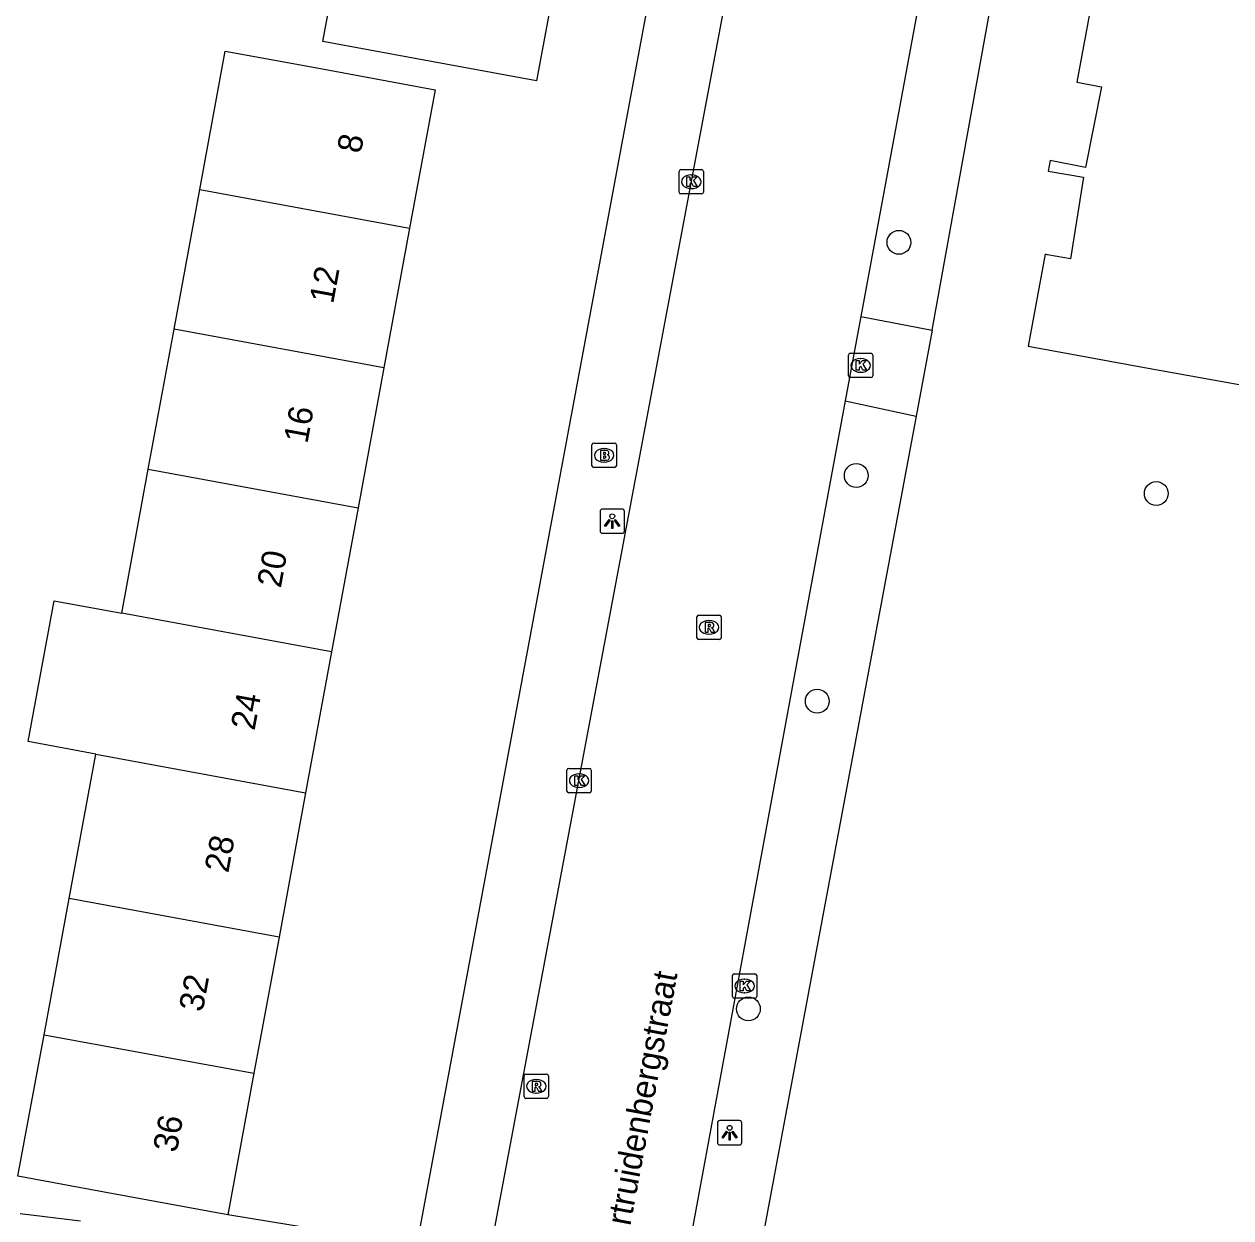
# Model space of a CAD drawing. Extents: x 158087 to 159494, y 382905 to 383981.
# Drawn here: x 158547.97 to 158597.49, y 383276.3 to 383325.28 of the extents above; entities that cross this region are included whole.
import ezdxf

# ---------------------------------------------------------------- set-up
doc = ezdxf.new("R2010")
doc.units = 0
for name, color, linetype in [('IMGEO_Boom', 7, 'Continuous'), ('IMGEO_Brandkraan', 7, 'Continuous'), ('IMGEO_Kolk', 7, 'Continuous'), ('IMGEO_Lichtpunt', 7, 'Continuous'), ('IMGEO_Openbare_ruimte_label', 7, 'Continuous'), ('IMGEO_Pand', 7, 'Continuous'), ('IMGEO_Pand_nummerreeks', 7, 'Continuous'), ('IMGEO_Rijbaan_lokaal_open', 7, 'Continuous'), ('IMGEO_Rioolput', 7, 'Continuous'), ('IMGEO_Voetpad_open', 7, 'Continuous')]:
    doc.layers.add(name, color=color, linetype=linetype)

msp = doc.modelspace()

# ---------------------------------------------------------------- linework, layer by layer
at = {"layer": 'IMGEO_Boom'}
for centre in [(158583.874, 383316.324), (158582.123, 383306.758), (158594.435, 383306.017), (158580.522, 383297.499), (158577.694, 383284.871)]:
    msp.add_circle(centre, 0.489, dxfattribs=at)
at = {"layer": 'IMGEO_Brandkraan'}
for p, q in [((158571.276, 383307.16), (158571.276, 383308.012)), ((158571.351, 383308.086), (158572.203, 383308.086)), ((158572.277, 383308.012), (158572.277, 383307.16)), ((158571.764, 383307.866), (158571.789, 383307.866)), ((158572.203, 383307.086), (158571.351, 383307.086)), ((158571.787, 383307.306), (158571.762, 383307.306))]:
    msp.add_line(p, q, dxfattribs=at)
for points in [[(158571.276, 383307.16), (158571.276, 383308.012)], [(158571.351, 383308.086), (158572.203, 383308.086)], [(158572.277, 383308.012), (158572.277, 383307.16)], [(158571.624, 383307.786), (158571.624, 383307.386), (158571.837, 383307.386)], [(158571.855, 383307.786), (158571.624, 383307.786)], [(158571.803, 383307.705), (158571.749, 383307.705), (158571.749, 383307.629)], [(158571.749, 383307.629), (158571.802, 383307.629)], [(158571.811, 383307.553), (158571.749, 383307.553), (158571.749, 383307.472)], [(158572.203, 383307.086), (158571.351, 383307.086)], [(158571.749, 383307.472), (158571.811, 383307.472)]]:
    msp.add_lwpolyline(points, dxfattribs=at)
for centre, radius, start, end in [((158571.353, 383308.01), 0.0765, 91.552, 178.448), ((158571.353, 383308.01), 0.0765, 91.552, 178.448), ((158572.201, 383308.01), 0.0765, 1.552, 88.448), ((158572.201, 383308.01), 0.0765, 1.552, 88.448), ((158571.804, 383307.667), 0.0379, 267.8285, 90.9355), ((158571.812, 383307.512), 0.0404, 269.8759, 90.5077), ((158571.859, 383307.641), 0.145, 59.4692, 91.5367), ((158571.884, 383307.688), 0.0922, 285.5137, 58.1501), ((158571.889, 383307.496), 0.105, 301.3115, 78.989), ((158571.353, 383307.162), 0.0765, 181.552, 268.448), ((158571.353, 383307.162), 0.0765, 181.552, 268.448), ((158571.843, 383307.637), 0.251, 268.6676, 293.5347), ((158572.201, 383307.162), 0.0765, 271.552, 358.448), ((158572.201, 383307.162), 0.0765, 271.552, 358.448)]:
    msp.add_arc(centre, radius, start, end, dxfattribs=at)
for centre, major_axis, ratio, start_param, end_param in [((158571.763, 383307.586), (-0.387, 0.002), 0.722429, 4.712389, 7.853982), ((158571.788, 383307.586), (-0.39, 0.002), 0.717154, 1.570796, 4.712389)]:
    msp.add_ellipse(centre, major_axis=major_axis, ratio=ratio, start_param=start_param, end_param=end_param, dxfattribs=at)
at = {"layer": 'IMGEO_Kolk'}
for p, q in [((158574.851, 383318.384), (158574.851, 383319.236)), ((158574.926, 383319.31), (158575.778, 383319.31)), ((158575.339, 383319.09), (158575.364, 383319.09)), ((158575.852, 383319.236), (158575.852, 383318.384)), ((158575.362, 383318.53), (158575.337, 383318.53)), ((158575.778, 383318.31), (158574.926, 383318.31)), ((158581.8, 383310.847), (158581.8, 383311.699)), ((158581.875, 383311.773), (158582.727, 383311.773)), ((158582.288, 383311.553), (158582.313, 383311.553)), ((158582.801, 383311.699), (158582.801, 383310.847)), ((158582.311, 383310.993), (158582.286, 383310.993)), ((158582.727, 383310.773), (158581.875, 383310.773)), ((158570.248, 383293.813), (158570.248, 383294.665)), ((158570.323, 383294.739), (158571.175, 383294.739)), ((158571.249, 383294.665), (158571.249, 383293.813)), ((158570.736, 383294.519), (158570.761, 383294.519)), ((158571.175, 383293.739), (158570.323, 383293.739)), ((158570.759, 383293.959), (158570.734, 383293.959)), ((158577.039, 383285.386), (158577.039, 383286.238)), ((158577.114, 383286.312), (158577.966, 383286.312)), ((158578.04, 383286.238), (158578.04, 383285.386)), ((158577.527, 383286.092), (158577.552, 383286.092)), ((158577.966, 383285.312), (158577.114, 383285.312)), ((158577.55, 383285.532), (158577.525, 383285.532))]:
    msp.add_line(p, q, dxfattribs=at)
for points in [[(158574.851, 383318.384), (158574.851, 383319.236)], [(158574.926, 383319.31), (158575.778, 383319.31)], [(158575.172, 383319.01), (158575.295, 383319.01), (158575.295, 383318.859), (158575.425, 383319.01), (158575.589, 383319.01), (158575.443, 383318.859), (158575.596, 383318.61), (158575.444, 383318.61), (158575.359, 383318.774), (158575.295, 383318.707), (158575.295, 383318.61), (158575.172, 383318.61), (158575.172, 383319.01)], [(158575.852, 383319.236), (158575.852, 383318.384)], [(158575.778, 383318.31), (158574.926, 383318.31)], [(158581.8, 383310.847), (158581.8, 383311.699)], [(158581.875, 383311.773), (158582.727, 383311.773)], [(158582.121, 383311.473), (158582.244, 383311.473), (158582.244, 383311.322), (158582.374, 383311.473), (158582.538, 383311.473), (158582.392, 383311.322), (158582.545, 383311.073), (158582.393, 383311.073), (158582.308, 383311.237), (158582.244, 383311.17), (158582.244, 383311.073), (158582.121, 383311.073), (158582.121, 383311.473)], [(158582.801, 383311.699), (158582.801, 383310.847)], [(158582.727, 383310.773), (158581.875, 383310.773)], [(158570.248, 383293.813), (158570.248, 383294.665)], [(158570.323, 383294.739), (158571.175, 383294.739)], [(158571.249, 383294.665), (158571.249, 383293.813)], [(158570.569, 383294.439), (158570.692, 383294.439), (158570.692, 383294.288), (158570.822, 383294.439), (158570.986, 383294.439), (158570.84, 383294.288), (158570.993, 383294.039), (158570.841, 383294.039), (158570.756, 383294.203), (158570.692, 383294.136), (158570.692, 383294.039), (158570.569, 383294.039), (158570.569, 383294.439)], [(158571.175, 383293.739), (158570.323, 383293.739)], [(158577.039, 383285.386), (158577.039, 383286.238)], [(158577.114, 383286.312), (158577.966, 383286.312)], [(158578.04, 383286.238), (158578.04, 383285.386)], [(158577.36, 383286.012), (158577.483, 383286.012), (158577.483, 383285.861), (158577.613, 383286.012), (158577.777, 383286.012), (158577.631, 383285.861), (158577.784, 383285.612), (158577.632, 383285.612), (158577.547, 383285.776), (158577.483, 383285.709), (158577.483, 383285.612), (158577.36, 383285.612), (158577.36, 383286.012)], [(158577.966, 383285.312), (158577.114, 383285.312)]]:
    msp.add_lwpolyline(points, dxfattribs=at)
for centre, start, end in [((158574.928, 383319.234), 91.552, 178.448), ((158574.928, 383319.234), 91.552, 178.448), ((158575.776, 383319.234), 1.552, 88.448), ((158575.776, 383319.234), 1.552, 88.448), ((158574.928, 383318.386), 181.552, 268.448), ((158574.928, 383318.386), 181.552, 268.448), ((158575.776, 383318.386), 271.552, 358.448), ((158575.776, 383318.386), 271.552, 358.448), ((158581.877, 383311.697), 91.552, 178.448), ((158581.877, 383311.697), 91.552, 178.448), ((158582.725, 383311.697), 1.552, 88.448), ((158582.725, 383311.697), 1.552, 88.448), ((158581.877, 383310.849), 181.552, 268.448), ((158581.877, 383310.849), 181.552, 268.448), ((158582.725, 383310.849), 271.552, 358.448), ((158582.725, 383310.849), 271.552, 358.448), ((158570.325, 383294.663), 91.552, 178.448), ((158570.325, 383294.663), 91.552, 178.448), ((158571.173, 383294.663), 1.552, 88.448), ((158571.173, 383294.663), 1.552, 88.448), ((158570.325, 383293.815), 181.552, 268.448), ((158570.325, 383293.815), 181.552, 268.448), ((158571.173, 383293.815), 271.552, 358.448), ((158571.173, 383293.815), 271.552, 358.448), ((158577.116, 383286.236), 91.552, 178.448), ((158577.116, 383286.236), 91.552, 178.448), ((158577.964, 383286.236), 1.552, 88.448), ((158577.964, 383286.236), 1.552, 88.448), ((158577.116, 383285.388), 181.552, 268.448), ((158577.116, 383285.388), 181.552, 268.448), ((158577.964, 383285.388), 271.552, 358.448), ((158577.964, 383285.388), 271.552, 358.448)]:
    msp.add_arc(centre, 0.0765, start, end, dxfattribs=at)
for centre, major_axis, ratio, start_param, end_param in [((158575.338, 383318.81), (-0.387, 0.002), 0.722429, 4.712389, 7.853982), ((158575.363, 383318.81), (-0.39, 0.002), 0.717154, 1.570796, 4.712389), ((158582.287, 383311.273), (-0.387, 0.002), 0.722429, 4.712389, 7.853982), ((158582.312, 383311.273), (-0.39, 0.002), 0.717154, 1.570796, 4.712389), ((158570.735, 383294.239), (-0.387, 0.002), 0.722429, 4.712389, 7.853982), ((158570.76, 383294.239), (-0.39, 0.002), 0.717154, 1.570796, 4.712389), ((158577.526, 383285.812), (-0.387, 0.002), 0.722429, 4.712389, 7.853982), ((158577.551, 383285.812), (-0.39, 0.002), 0.717154, 1.570796, 4.712389)]:
    msp.add_ellipse(centre, major_axis=major_axis, ratio=ratio, start_param=start_param, end_param=end_param, dxfattribs=at)
at = {"layer": 'IMGEO_Lichtpunt'}
for p, q in [((158571.61, 383305.287), (158571.61, 383304.48)), ((158571.61, 383305.287), (158571.61, 383304.48)), ((158572.512, 383305.382), (158571.704, 383305.382)), ((158572.512, 383305.382), (158571.704, 383305.382)), ((158572.606, 383304.48), (158572.606, 383305.287)), ((158572.606, 383304.48), (158572.606, 383305.287)), ((158571.704, 383304.386), (158572.512, 383304.386)), ((158571.704, 383304.386), (158572.512, 383304.386)), ((158577.329, 383280.291), (158576.521, 383280.291)), ((158577.329, 383280.291), (158576.521, 383280.291)), ((158576.427, 383280.196), (158576.427, 383279.389)), ((158576.427, 383280.196), (158576.427, 383279.389)), ((158577.423, 383279.389), (158577.423, 383280.196)), ((158577.423, 383279.389), (158577.423, 383280.196)), ((158576.521, 383279.295), (158577.329, 383279.295)), ((158576.521, 383279.295), (158577.329, 383279.295))]:
    msp.add_line(p, q, dxfattribs=at)
for points in [[(158571.984, 383304.951), (158572.023, 383304.923), (158571.835, 383304.661), (158571.797, 383304.688), (158571.984, 383304.951)], [(158572.086, 383304.903), (158572.133, 383304.903), (158572.133, 383304.581), (158572.086, 383304.581), (158572.086, 383304.903)], [(158572.196, 383304.923), (158572.234, 383304.95), (158572.421, 383304.688), (158572.382, 383304.66), (158572.196, 383304.923)], [(158576.801, 383279.86), (158576.84, 383279.832), (158576.652, 383279.57), (158576.614, 383279.597), (158576.801, 383279.86)], [(158576.903, 383279.812), (158576.95, 383279.812), (158576.95, 383279.49), (158576.903, 383279.49), (158576.903, 383279.812)], [(158577.013, 383279.832), (158577.051, 383279.859), (158577.238, 383279.597), (158577.199, 383279.569), (158577.013, 383279.832)]]:
    msp.add_lwpolyline(points, dxfattribs=at)
for centre in [(158572.109, 383305.085), (158576.926, 383279.994)]:
    msp.add_circle(centre, 0.0994, dxfattribs=at)
for centre, start, end in [((158571.704, 383305.287), 90, 180), ((158571.704, 383305.287), 90, 180), ((158572.512, 383305.287), 0, 90), ((158572.512, 383305.287), 0, 90), ((158571.704, 383304.48), 180, 270), ((158571.704, 383304.48), 180, 270), ((158572.512, 383304.48), 270, 0), ((158572.512, 383304.48), 270, 360), ((158576.521, 383280.196), 90, 180), ((158576.521, 383280.196), 90, 180), ((158577.329, 383280.196), 0, 90), ((158577.329, 383280.196), 0, 90), ((158576.521, 383279.389), 180, 270), ((158576.521, 383279.389), 180, 270), ((158577.329, 383279.389), 270, 0), ((158577.329, 383279.389), 270, 360)]:
    msp.add_arc(centre, 0.0946, start, end, dxfattribs=at)
at = {"layer": 'IMGEO_Pand'}
for points in [[(158599.482, 383347.068), (158596.791, 383347.973), (158596.125, 383343.926), (158595.09, 383344.142), (158593.778, 383337.052), (158594.823, 383336.845), (158594.137, 383333.568), (158592.674, 383333.836), (158592.591, 383333.398), (158594.085, 383333.132), (158593.521, 383329.798), (158592.481, 383329.996), (158591.168, 383322.9), (158592.192, 383322.707), (158591.532, 383319.397), (158590.075, 383319.679), (158589.993, 383319.25), (158591.45, 383319.003), (158590.916, 383315.65), (158589.975, 383315.818), (158589.874, 383315.836), (158589.175, 383312.06), (158594.095, 383311.168), (158597.83, 383310.49)], [(158570.051, 383328.609), (158569.007, 383322.944), (158564.09, 383323.85), (158560.238, 383324.561), (158560.74, 383327.288), (158555.322, 383328.286), (158554.794, 383328.384), (158555.341, 383331.35), (158555.868, 383331.251)], [(158555.182, 383318.495), (158556.228, 383324.173), (158559.924, 383323.493), (158564.841, 383322.587), (158563.794, 383316.908)], [(158554.125, 383312.764), (158555.182, 383318.495)], [(158555.182, 383318.495), (158563.794, 383316.908)], [(158563.794, 383316.908), (158562.738, 383311.177)], [(158553.066, 383307.015), (158554.125, 383312.764)], [(158562.738, 383311.177), (158554.125, 383312.764)], [(158562.738, 383311.177), (158561.679, 383305.428)], [(158551.977, 383301.105), (158553.066, 383307.015)], [(158553.066, 383307.015), (158561.679, 383305.428)], [(158561.679, 383305.428), (158560.59, 383299.518)], [(158550.912, 383295.328), (158548.137, 383295.84), (158549.202, 383301.617), (158551.977, 383301.105)], [(158560.59, 383299.518), (158551.977, 383301.105)], [(158560.59, 383299.518), (158559.525, 383293.742)], [(158549.821, 383289.409), (158550.912, 383295.328)], [(158550.912, 383295.328), (158559.525, 383293.742)], [(158559.525, 383293.742), (158558.434, 383287.823)], [(158548.791, 383283.816), (158549.821, 383289.409)], [(158558.434, 383287.823), (158549.821, 383289.409)], [(158558.434, 383287.823), (158557.404, 383282.23)], [(158547.72, 383278.007), (158548.791, 383283.816)], [(158548.791, 383283.816), (158557.404, 383282.23)], [(158557.404, 383282.23), (158556.333, 383276.42)], [(158556.333, 383276.42), (158551.416, 383277.326), (158547.72, 383278.007)]]:
    msp.add_lwpolyline(points, dxfattribs=at)
at = {"layer": 'IMGEO_Rijbaan_lokaal_open'}
for points in [[(158591.055, 383360.592), (158590.03, 383354.993), (158582.307, 383313.283)], [(158566.865, 383273.653), (158579.328, 383339.933)], [(158582.307, 383313.283), (158581.664, 383309.815)], [(158581.664, 383309.815), (158579.736, 383299.401), (158570.635, 383250), (158570.464, 383249.119)]]:
    msp.add_lwpolyline(points, dxfattribs=at)
at = {"layer": 'IMGEO_Rioolput'}
for p, q in [((158575.58, 383300.102), (158575.58, 383300.954)), ((158575.655, 383301.028), (158576.507, 383301.028)), ((158576.068, 383300.808), (158576.093, 383300.808)), ((158576.581, 383300.954), (158576.581, 383300.102)), ((158576.091, 383300.248), (158576.066, 383300.248)), ((158576.507, 383300.028), (158575.655, 383300.028)), ((158568.489, 383281.273), (158568.489, 383282.125)), ((158568.564, 383282.199), (158569.416, 383282.199)), ((158568.977, 383281.979), (158569.002, 383281.979)), ((158569.49, 383282.125), (158569.49, 383281.273)), ((158569, 383281.419), (158568.975, 383281.419)), ((158569.416, 383281.199), (158568.564, 383281.199))]:
    msp.add_line(p, q, dxfattribs=at)
for points in [[(158575.58, 383300.102), (158575.58, 383300.954)], [(158575.655, 383301.028), (158576.507, 383301.028)], [(158576.169, 383300.726), (158575.917, 383300.728), (158575.917, 383300.328)], [(158576.095, 383300.647), (158576.041, 383300.647), (158576.041, 383300.566)], [(158576.041, 383300.566), (158576.093, 383300.566)], [(158576.581, 383300.954), (158576.581, 383300.102)], [(158575.917, 383300.328), (158576.041, 383300.328), (158576.041, 383300.49), (158576.052, 383300.49)], [(158576.099, 383300.461), (158576.17, 383300.328), (158576.31, 383300.328), (158576.245, 383300.454)], [(158576.507, 383300.028), (158575.655, 383300.028)], [(158568.489, 383281.273), (158568.489, 383282.125)], [(158568.564, 383282.199), (158569.416, 383282.199)], [(158569.078, 383281.897), (158568.826, 383281.899), (158568.826, 383281.499)], [(158569.004, 383281.818), (158568.95, 383281.818), (158568.95, 383281.737)], [(158569.49, 383282.125), (158569.49, 383281.273)], [(158568.826, 383281.499), (158568.95, 383281.499), (158568.95, 383281.661), (158568.961, 383281.661)], [(158568.95, 383281.737), (158569.002, 383281.737)], [(158569.008, 383281.632), (158569.079, 383281.499), (158569.219, 383281.499), (158569.154, 383281.625)], [(158569.416, 383281.199), (158568.564, 383281.199)]]:
    msp.add_lwpolyline(points, dxfattribs=at)
for centre, radius, start, end in [((158575.657, 383300.952), 0.0765, 91.552, 178.448), ((158575.657, 383300.952), 0.0765, 91.552, 178.448), ((158576.077, 383300.755), 0.19, 274.7715, 282.9687), ((158576.101, 383300.551), 0.0964, 77.0061, 93.1865), ((158576.115, 383300.608), 0.0378, 276.6634, 79.6772), ((158576.168, 383300.616), 0.109, 350.3612, 89.416), ((158576.166, 383300.616), 0.112, 277.5842, 350.9817), ((158576.505, 383300.952), 0.0765, 1.552, 88.448), ((158576.505, 383300.952), 0.0765, 1.552, 88.448), ((158575.657, 383300.104), 0.0765, 181.552, 268.448), ((158575.657, 383300.104), 0.0765, 181.552, 268.448), ((158576.051, 383300.437), 0.0533, 26.0293, 88.6989), ((158576.15, 383300.401), 0.108, 29.5134, 73.7905), ((158576.505, 383300.104), 0.0765, 271.552, 358.448), ((158576.505, 383300.104), 0.0765, 271.552, 358.448), ((158568.566, 383282.123), 0.0765, 91.552, 178.448), ((158568.566, 383282.123), 0.0765, 91.552, 178.448), ((158568.986, 383281.926), 0.19, 274.7715, 282.9687), ((158569.01, 383281.722), 0.0964, 77.0061, 93.1865), ((158569.024, 383281.779), 0.0378, 276.6634, 79.6772), ((158569.077, 383281.787), 0.109, 350.3612, 89.416), ((158569.075, 383281.787), 0.112, 277.5842, 350.9817), ((158569.414, 383282.123), 0.0765, 1.552, 88.448), ((158569.414, 383282.123), 0.0765, 1.552, 88.448), ((158568.566, 383281.275), 0.0765, 181.552, 268.448), ((158568.566, 383281.275), 0.0765, 181.552, 268.448), ((158568.96, 383281.608), 0.0533, 26.0293, 88.6989), ((158569.059, 383281.572), 0.108, 29.5134, 73.7905), ((158569.414, 383281.275), 0.0765, 271.552, 358.448), ((158569.414, 383281.275), 0.0765, 271.552, 358.448)]:
    msp.add_arc(centre, radius, start, end, dxfattribs=at)
for centre, major_axis, ratio, start_param, end_param in [((158576.067, 383300.528), (-0.387, 0.002), 0.722429, 4.712389, 7.853982), ((158576.092, 383300.528), (-0.39, 0.002), 0.717154, 1.570796, 4.712389), ((158568.976, 383281.699), (-0.387, 0.002), 0.722429, 4.712389, 7.853982), ((158569.001, 383281.699), (-0.39, 0.002), 0.717154, 1.570796, 4.712389)]:
    msp.add_ellipse(centre, major_axis=major_axis, ratio=ratio, start_param=start_param, end_param=end_param, dxfattribs=at)
at = {"layer": 'IMGEO_Voetpad_open'}
for points in [[(158585.243, 383312.721), (158592.385, 383352.344), (158593.193, 383356.252), (158593.935, 383359.866)], [(158564.087, 383275.159), (158576.054, 383339.428)], [(158582.307, 383313.283), (158585.243, 383312.721)], [(158585.243, 383312.721), (158584.576, 383309.191)], [(158581.664, 383309.815), (158584.576, 383309.191)], [(158584.576, 383309.191), (158573.515, 383250), (158565.366, 383205.337), (158565.715, 383205.279), (158560.261, 383175.849), (158564.517, 383174.829)], [(158547.812, 383276.478), (158550.288, 383276.18)], [(158564.087, 383275.159), (158556.333, 383276.42)]]:
    msp.add_lwpolyline(points, dxfattribs=at)

# ---------------------------------------------------------------- texts
at = {"layer": 'IMGEO_Openbare_ruimte_label'}
msp.add_text('Geertruidenbergstraat', height=1, rotation=79.3979, dxfattribs=at).set_placement((158572.384, 383273.455))
at = {"layer": 'IMGEO_Pand_nummerreeks'}
for s, rotation, p in [('8', 79.5541, (158561.79, 383319.938)), ('12', 79.5597, (158560.654, 383313.773)), ('16', 79.561, (158559.597, 383308.036)), ('20', 79.5574, (158558.506, 383302.113)), ('24', 79.5609, (158557.428, 383296.268)), ('28', 79.5542, (158556.352, 383290.425)), ('32', 79.5537, (158555.301, 383284.717)), ('36', 79.5537, (158554.237, 383278.949))]:
    msp.add_text(s, height=1, rotation=rotation, dxfattribs=at).set_placement(p)

doc.saveas('drawing.dxf')
